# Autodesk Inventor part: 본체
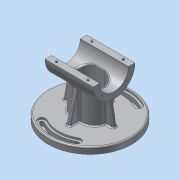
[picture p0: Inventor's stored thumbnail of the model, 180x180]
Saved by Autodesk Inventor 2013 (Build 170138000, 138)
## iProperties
Created: 2015-12
Part Number: 본체
Material: 알루미늄 6061
Document SubType Name: Modeling
Designer: mduedu
Density: 2.71 g/cm^3
Mass: 594.298 g
Surface Area: 580.345 cm^2
Volume: 219.298 cm^3
Author: mduedu
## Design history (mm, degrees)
sketch "스케치1"
  geometry: C1 r 65 at (0, 0); 1 further point
  constraints: 1 centre point, 1 coincident
  dimensions: "d124" = 130 diameter of C1
extrude "돌출1" new body sketch "스케치1" distance "d3" = 10; taper "d4" = 0 deg
sketch "스케치2"
  geometry: C1 r 32.5 at (80, 0); 1 further point
  constraints: 1 centre point, 1 horizontal alignment
  dimensions: "d5" = 65 diameter of C1; "d125" = 80 distance of C1.centre point (0, 0)
extrude "돌출2" join sketch "스케치2" stored distance "d7" = 75; taper "d8" = 0 deg
sketch "스케치3"
  geometry: L1 (-27.5, -20)-(27.5, -20); L2 (27.5, -20)-(27.5, 20); L3 (27.5, 20)-(-27.5, 20); L4 (-27.5, 20)-(-27.5, -20); L5 (-27.5, -20)-(27.5, 20); L6 (27.5, -20)-(-27.5, 20); 1 further point
  constraints: 12 end point, 2 midpoint, 2 parallel, 1 horizontal, 1 perpendicular
  dimensions: "d9" = 55 distance of L2.end L3.end; "d11" = 40 distance of L1.end L2.end
extrude "돌출3" new body sketch "스케치3" stored distance "d12" = 75; taper "d13" = 0 deg
fillet "모깎기1"
fillet "모깎기2"
feature "결합1"
  node "솔리드2"
sketch "스케치4"
  geometry: L1 (-37.5, 47.5)-(37.5, 47.5) reference; L2 (32.5, 47.5)-(39.112, 10); L3 (37.5, 47.5)-(37.5, 112.5) reference; L4 (65, 10)-(-65, 10) reference; 1 further point
  constraints: 2 end point, 2 point on line
  dimensions: "d15" = 5 distance from line of L2.start L3; "d126" = 80 deg angle of L2 L1
sketch "스케치5"
  geometry: L1 (10, 35)-(56.569, 22.522); L2 (10, -65)-(10, 65) reference; L3 (10, 20)-(54.383, 20) reference; A1 r 32.5 centre (80, 0) between (56.569, 22.522) and (54.383, 20) reference; 1 further point
  constraints: 2 end point, 1 point on circle, 1 point on line
  dimensions: "d127" = 75 deg angle of L1 L2; "d128" = 15 distance of L1.start L3.start
feature "리브1" dims "d19" = 1, "d20" = 6, "d21" = 0, "d22" = 0, "d23" = 1, "d24" = 1
feature "리브2" dims "d25" = 1, "d26" = 6, "d27" = 0, "d28" = 0, "d29" = 1, "d30" = 1
fillet "모깎기4" dims "d31" = 2
fillet "모깎기5" dims "d32" = 2
fillet "모깎기6" dims "d33" = 2
fillet "모깎기7" dims "d41" = 2
hole "구멍2" diameter "d44" = 45; stored, may be unused: countersink angle "d48" = 90 deg, drill point angle "d50" = 118 deg; dims "d42" = 10, "d43" = 10, "d45" = 6, "d46" = 4, "d47" = 2, "d49" = 8
sketch "스케치7" dims "d52" = 26.5
  geometry: L1 (0, 0)-(32.5, 0); L2 (0, 0)-(22.981, 22.981); A1 r 32.5 centre (0, 0) between (32.5, 0) and (22.981, 22.981) reference; 3 further points
  constraints: 4 end point, 2 point on circle, 1 coincident, 1 horizontal, 1 point on line, 3 other
  dimensions: "d51" = 45 deg angle of L2 L1
hole "구멍3" sketch "스케치7" at (18.738, 18.738) diameter "d54" = 2.459; stored, may be unused: countersink angle "d58" = 90 deg, drill point angle "d60" = 118 deg; dims "d55" = 8, "d56" = 4, "d57" = 2, "d59" = 10
sketch "스케치9"
  geometry: L1 (-75, 82.5)-(75, 82.5); L2 (75, 82.5)-(75, 0); L3 (75, 0)-(-75, 0); L4 (-75, 0)-(-75, 82.5); C1 r 32.5 at (0, 0) reference; 2 further points
  constraints: 8 end point, 2 parallel, 1 coincident, 1 horizontal, 1 midpoint, 1 perpendicular
  dimensions: "d71" = 50 distance edge to line of C1 L1; "d116" = 150 distance between parallel lines of L2 L4
extrude "돌출5" cut sketch "스케치9" stored distance "d73" = 0; taper "d74" = 0 deg
node "작업 평면1"
sketch "스케치10"
  geometry: L1 (-7.5, 15)-(7.5, 15); L2 (-7.5, -15)-(7.5, -15); A1 r 20 centre (-7.5, 0) between (-7.5, 20) and (-26.977, 4.545) reference; A2 r 20 centre (7.5, 0) between (26.977, 4.545) and (7.5, 20) reference; A3 r 15 centre (-7.5, 0) between (-7.5, 15) and (-7.5, -15); A4 r 15 centre (7.5, 0) between (7.5, -15) and (7.5, 15); 1 further point
  constraints: 7 point on circle, 4 end point, 4 tangent, 3 point on line, 2 centre point, 2 coincident, 1 horizontal
  dimensions: "d77" = 5 radial gap between concentric circles of A3 A1
extrude "돌출6" cut sketch "스케치10" stored distance "d78" = 50; taper "d79" = 0 deg
fillet "모깎기10" dims "d80" = 3
sketch "스케치11"
  geometry: 2 further points
  constraints: 1 coincident
hole "구멍4" sketch "스케치11" at (0, 0) diameter "d81" = 12; stored, may be unused: countersink angle "d85" = 90 deg, drill point angle "d87" = 118 deg; dims "d82" = 8, "d83" = 40, "d84" = 10, "d86" = 10
sketch "스케치12"
  geometry: C1 r 10 at (0, 0); 1 further point
  constraints: 1 centre point, 1 coincident
  dimensions: "d88" = 20 diameter of C1
extrude "돌출7" cut sketch "스케치12" distance "d89" = 5; taper "d90" = 0 deg
chamfer "모따기1" distance "d91" = 1; stored, may be unused: second distance "d92" = 2, angle "d93" = 45 deg
fillet "모깎기11" dims "d94" = 0.5
fillet "모깎기12" dims "d115" = 0.3
sketch "스케치15"
  geometry: L1 (-75, 55)-(-75, 65) reference; L2 (0, 65)-(0, 55) reference; L3 (-75, 60)-(0, 60); C1 r 1.5 at (-62, 60); 1 further point
  constraints: 2 end point, 2 midpoint, 1 centre point, 1 point on line
  dimensions: "d117" = 3 diameter of C1; "d118" = 13 distance from line of C1.centre L1
extrude "돌출8" join sketch "스케치15" distance "d119" = 1.8; taper "d120" = 0 deg
chamfer "모따기2" distance "d121" = 0.5; stored, may be unused: second distance "d122" = 2, angle "d123" = 45 deg
sketch "스케치16"
  geometry: L1 (0, 0)-(61, 0); L2 (0, 0)-(30.5, 52.828); L3 (0, 0)-(-30.5, 52.828); L4 (0, 0)-(-61, 0); A1 r 55 centre (0, 0) between (-27.5, 47.631) and (27.5, 47.631); A2 r 61 centre (0, 0) between (-30.5, 52.828) and (30.5, 52.828); A3 r 49 centre (0, 0) between (-24.5, 42.435) and (24.5, 42.435); A4 r 6 centre (-27.5, 47.631) between (-30.5, 52.828) and (-24.5, 42.435); A5 r 6 centre (27.5, 47.631) between (30.5, 52.828) and (24.5, 42.435); A6 r 49 centre (0, 0) between (24.5, 42.435) and (-24.5, 42.435); A7 r 61 centre (0, 0) between (30.5, 52.828) and (-30.5, 52.828); 1 further point
  constraints: 15 point on circle, 8 end point, 7 centre point, 2 point on line, 1 coincident, 1 horizontal, 10 other
  dimensions: "d129" = 110 diameter of A1; "d130" = 6 radial gap between concentric circles of A1 A2; "d131" = 6 radial gap between concentric circles of A3 A1; "d134" = 180 deg dimension on point (0, 0) L1.end L4.end
extrude "돌출9" cut sketch "스케치16" distance "d136" = 3; taper "d137" = 0 deg
sketch "스케치17"
  geometry: A1 r 6 centre (27.5, 47.631) between (24.5, 42.435) and (30.5, 52.828) reference; A2 r 61 centre (0, 0) between (30.5, 52.828) and (-30.5, 52.828) reference; A3 r 6 centre (-27.5, 47.631) between (-30.5, 52.828) and (-24.5, 42.435) reference; A4 r 49 centre (0, 0) between (24.5, 42.435) and (-24.5, 42.435) reference; A5 r 58 centre (0, 0) between (29, 50.229) and (-29, 50.229); A6 r 3 centre (27.5, 47.631) between (26, 45.033) and (29, 50.229); A7 r 52 centre (0, 0) between (26, 45.033) and (-26, 45.033); A8 r 3 centre (-27.5, 47.631) between (-29, 50.229) and (-26, 45.033); 1 further point
  constraints: 8 point on circle, 4 centre point, 3 other
  dimensions: "d138" = 3 radial gap between concentric circles of A5 A2
extrude "돌출10" cut sketch "스케치17" stored distance "d139" = 3; taper "d140" = 0 deg
node "솔리드1"
mirror "대칭1"
mirror "대칭2"
pattern_circular "원형 패턴1" dims angle "d62" = 360 deg
mirror "대칭3"
mirror "대칭5"
mirror "대칭6"
mirror "대칭7"
node "투영된 루프1"
